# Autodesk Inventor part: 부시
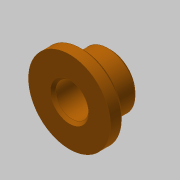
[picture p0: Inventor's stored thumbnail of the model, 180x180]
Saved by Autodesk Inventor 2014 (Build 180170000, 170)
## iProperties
Created: 2016-02
Part Number: 부시
Material: 스테인리스강
Document SubType Name: Modeling
Designer: mduedu
Density: 8.08 g/cm^3
Mass: 39.4553 g
Surface Area: 27.3717 cm^2
Volume: 4.88308 cm^3
Appearance: 주황색
Author: mduedu
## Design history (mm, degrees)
sketch "스케치1"
  geometry: C1 r 15 at (0, 0); 1 further point
  constraints: 1 centre point, 1 coincident
  dimensions: "d0" = 30 diameter of C1
extrude "돌출1" new body sketch "스케치1" distance "d1" = 5; taper "d2" = 0 deg
sketch "스케치2"
  geometry: C1 r 10 at (0, 0); 1 further point
  constraints: 1 centre point, 1 coincident
  dimensions: "d3" = 20 diameter of C1
extrude "돌출2" join sketch "스케치2" distance "d4" = 10; taper "d5" = 0 deg
hole "구멍1" diameter "d8" = 12; stored, may be unused: countersink angle "d12" = 90 deg, drill point angle "d14" = 118 deg; dims "d9" = 6, "d10" = 4, "d11" = 2, "d13" = 8, "d15" = 10, "d16" = 10
chamfer "모따기1" distance "d17" = 1; stored, may be unused: second distance "d18" = 2, angle "d19" = 45 deg
chamfer "모따기2" distance "d20" = 1; stored, may be unused: second distance "d21" = 2, angle "d22" = 45 deg
chamfer "모따기3" distance "d23" = 1; stored, may be unused: second distance "d24" = 2, angle "d25" = 45 deg
node "솔리드1"
